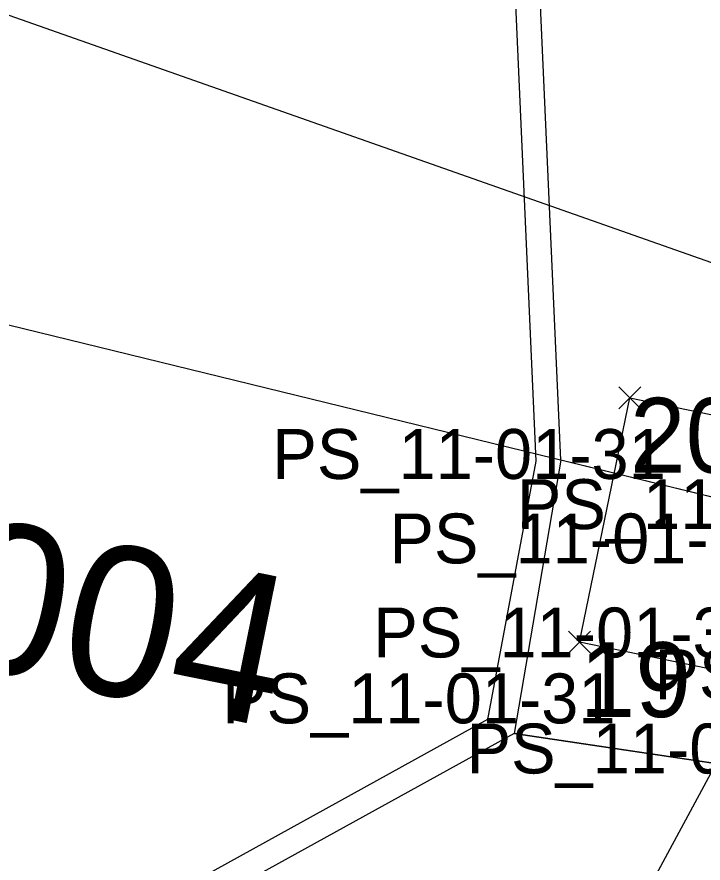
# Model space of a CAD drawing. Extents: x -728800 to -728100, y -1073200 to -1072700.
# Drawn here: x -728521.37 to -728515.87, y -1073048.35 to -1073041.57 of the extents above; entities that cross this region are included whole.
import ezdxf

# ---------------------------------------------------------------- set-up
doc = ezdxf.new("R2010")
doc.units = 0
for name, color, linetype in [('_NOR-šraf_zeleň', 7, 'Continuous'), ('A1_OBVOD Spravy železnic', 7, 'Continuous'), ('A2_OBVOD STAVBY', 7, 'Continuous'), ('B1_body_poloha', 7, 'Continuous'), ('B2_body_číslo', 7, 'Continuous'), ('B3_body_popiska', 7, 'Continuous'), ('B4_Bodové pole', 7, 'Continuous'), ('KOS_kabelová trasa', 7, 'Continuous'), ('ZA_01_Trvalý_pro_SŽDC_dle_UMVZST', 7, 'Continuous'), ('ZA_02_Dočasný_do_1_roku', 7, 'Continuous')]:
    doc.layers.add(name, color=color, linetype=linetype)

msp = doc.modelspace()

# ---------------------------------------------------------------- linework, layer by layer
at = {"layer": '_NOR-šraf_zeleň'}
msp.add_lwpolyline([(-728518.2797, -1073052.2165), (-728517.0623, -1073049.9587), (-728515.0597, -1073046.2449)], dxfattribs=at)
at = {"layer": 'A1_OBVOD Spravy železnic'}
msp.add_lwpolyline([(-728582.13, -1073004.22), (-728564.68, -1073020.02), (-728543.86, -1073026.9), (-728510.71, -1073032.54), (-728510.22, -1073036.28), (-728509.4149, -1073042.1854), (-728509.9, -1073046.86), (-728541.12, -1073039.22), (-728572.55, -1073027.78)], dxfattribs=at)
at = {"layer": 'A2_OBVOD STAVBY'}
for points in [[(-728564.1639, -1073015.5228), (-728556.4249, -1073019.4306), (-728548.1404, -1073022.8333), (-728542.882, -1073024.6206), (-728538.694, -1073025.349), (-728534.1395, -1073025.7372), (-728532.6639, -1073025.7875), (-728522.2323, -1073025.8063), (-728521.4876, -1073028.3203), (-728521.5447, -1073030.7259), (-728521.5937, -1073032.7876), (-728517.7546, -1073032.8788), (-728517.2093, -1073045.1291)], [(-728517.2093, -1073045.1291), (-728517.5964, -1073047.2005), (-728520.5688, -1073048.8422), (-728522.4417, -1073049.4936), (-728521.3538, -1073052.6217), (-728520.3306, -1073054.1859), (-728521.7354, -1073059.131)]]:
    msp.add_lwpolyline(points, dxfattribs=at)
at = {"layer": 'B1_body_poloha'}
for p, q in [((-728516.5448, -1073044.5324), (-728516.368, -1073044.7091)), ((-728516.5448, -1073044.7091), (-728516.368, -1073044.5324)), ((-728516.9474, -1073046.4916), (-728516.7706, -1073046.6684)), ((-728516.9474, -1073046.6684), (-728516.7706, -1073046.4916))]:
    msp.add_line(p, q, dxfattribs=at)
at = {"layer": 'B2_body_číslo'}
for p, q in [((-728516.456, -1073044.621), (-728516.456, -1073044.621)), ((-728516.859, -1073046.58), (-728516.859, -1073046.58))]:
    msp.add_line(p, q, dxfattribs=at)
at = {"layer": 'B4_Bodové pole'}
msp.add_lwpolyline([(-728665.963, -1072915.444), (-728594.709, -1073015.734), (-728502.086, -1073048.369), (-728347.458, -1073023.537)], dxfattribs=at)
at = {"layer": 'KOS_kabelová trasa'}
msp.add_lwpolyline([(-728516.8591, -1073046.5798), (-728516.4564, -1073044.6207), (-728514.4973, -1073045.0235), (-728514.9, -1073046.9825)], close=True, dxfattribs=at)
at = {"layer": 'ZA_01_Trvalý_pro_SŽDC_dle_UMVZST'}
msp.add_lwpolyline([(-728502.83, -1073049.48), (-728501.19, -1073037.94), (-728500.7194, -1073036.1609), (-728510.3267, -1073035.4653), (-728510.22, -1073036.28), (-728509.42, -1073042.19), (-728509.9, -1073046.86), (-728517.0095, -1073045.1202), (-728517.3822, -1073047.3107), (-728510.2456, -1073048.3747)], dxfattribs=at)
at = {"layer": 'ZA_02_Dočasný_do_1_roku'}
for points in [[(-728510.3267, -1073035.4653), (-728509.4149, -1073042.1854), (-728509.9, -1073046.86), (-728517.0095, -1073045.1202), (-728517.2863, -1073038.9018)], [(-728515.2033, -1073056.8181), (-728511.1894, -1073055.1227), (-728508.5954, -1073049.5354), (-728508.4924, -1073048.6368), (-728517.3822, -1073047.3107), (-728520.487, -1073049.0255), (-728522.1871, -1073049.6168), (-728521.173, -1073052.5328), (-728520.1133, -1073054.1527), (-728521.5861, -1073059.3376)]]:
    msp.add_lwpolyline(points, dxfattribs=at)

# ---------------------------------------------------------------- texts
at = {"layer": 'B2_body_číslo'}
for s, p in [('20', (-728516.456, -1073045.221)), ('19', (-728516.859, -1073047.18))]:
    msp.add_text(s, height=0.6, dxfattribs=at).set_placement(p)
at = {"layer": 'B3_body_popiska'}
for p in [(-728519.321, -1073045.271), (-728517.362, -1073045.673), (-728518.383, -1073045.948), (-728518.512, -1073046.702), (-728516.26, -1073047.037), (-728519.724, -1073047.23), (-728517.765, -1073047.632)]:
    msp.add_text('PS_11-01-31', height=0.4, dxfattribs=at).set_placement(p)
at = {"layer": 'B4_Bodové pole'}
msp.add_text('4004', height=1.2, rotation=348.54326, dxfattribs=at).set_placement((-728522.827, -1073046.5591))

doc.saveas('drawing.dxf')
